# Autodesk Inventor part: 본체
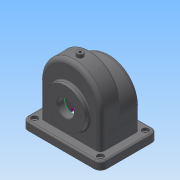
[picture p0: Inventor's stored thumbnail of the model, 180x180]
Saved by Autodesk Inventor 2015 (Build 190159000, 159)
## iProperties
Created: 2017-11
Part Number: 본체
Material: 알루미늄 6061
Document SubType Name: Modeling
Designer: user
Density: 2.7 g/cm^3
Appearance: 연회색
Mass: 1083.79 g
Surface Area: 1185.38 cm^2
Volume: 401.404 cm^3
Author: user
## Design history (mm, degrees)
sketch "스케치1"
  geometry: L1 (-58, 15)-(-58, -65); L2 (-58, -65)-(58, -65); L3 (58, -65)-(58, 15); C1 r 37.5 at (0, 0); A1 r 58 centre (0, 15) between (58, 15) and (-58, 15)
  constraints: 6 end point, 2 centre point, 2 point on circle, 1 perpendicular, 1 tangent, 1 vertical
extrude "돌출1" new body sketch "스케치1" distance "d18" = 9; taper "d19" = 0 deg
extrude "돌출2" join sketch "스케치1" distance "d20" = 38; taper "d21" = 0 deg
node "작업 평면1"
sketch "스케치2"
  geometry: C1 r 31 at (0, 0); 1 further point
  constraints: 1 centre point, 1 coincident
extrude "돌출3" join sketch "스케치2" distance "d30" = 10; taper "d31" = 0 deg
sketch "스케치3"
  geometry: L1 (58, -8)-(58, -65); L2 (58, -65)-(-58, -65); L3 (-58, -65)-(-58, -8); A1 r 58 centre (0, -8) between (58, -8) and (-58, -8); 1 further point
  constraints: 6 end point, 2 point on circle, 1 centre point, 1 perpendicular, 1 vertical
extrude "돌출4" join sketch "스케치3" distance "d39" = 38; taper "d40" = 0 deg
sketch "스케치4"
  geometry: C1 r 37.5 at (0, 0) reference; C2 r 16 at (0, 0)
  constraints: 1 centre point, 1 coincident
  dimensions: "d41" = 32 diameter of C2
extrude "돌출5" cut sketch "스케치4" distance "d42" = 14; taper "d43" = 0 deg
sketch "스케치5"
  geometry: L1 (-53, 14.446)-(-53, -65.554); L2 (53, 14.446)-(53, -65.554); L3 (-53, -65.554)-(53, -65.554); C1 r 16 at (0, 0) reference; A1 r 53 centre (0, 14.446) between (53, 14.446) and (-53, 14.446); A2 r 53 centre (0, -8.554) between (53, -8.554) and (-53, -8.554)
  constraints: 6 end point, 4 point on circle, 2 centre point, 2 point on line, 2 tangent, 2 vertical, 1 horizontal
extrude "돌출6" cut sketch "스케치5" distance "d49" = 66; taper "d50" = 0 deg
extrude "돌출7" cut sketch "스케치5" distance "d51" = 28; taper "d52" = 0 deg
extrude "돌출8" cut sketch "스케치5" distance "d53" = 95; taper "d54" = 0 deg
sketch "스케치6"
  geometry: L1 (133, 17)-(-17, 17); L2 (-17, 17)-(-17, -93); L3 (-17, -93)-(133, -93); L4 (133, 17)-(133, -93); L5 (-17, 17)-(-17, 5); L6 (-17, 17)-(-5, 17); L7 (133, -93)-(133, -81); L8 (133, -93)-(121, -93); L9 (116, 0)-(0, 0); L10 (0, 0)-(0, -76); L11 (0, -76)-(116, -76); L12 (116, -76)-(116, 0); L13 (111, -5)-(5, -5); L14 (5, -5)-(5, -71); L15 (5, -71)-(111, -71); L16 (111, -71)-(111, -5); C1 r 6 at (121, 5); C2 r 6 at (121, -81); C3 r 6 at (-5, -81); C4 r 6 at (-5, 5); C5 r 2.5 at (121, 5); C6 r 2.5 at (121, -81); C7 r 2.5 at (-5, -81); C8 r 2.5 at (-5, 5); 1 further point
  constraints: 32 end point, 8 centre point, 4 coincident, 4 parallel, 4 point on line, 3 perpendicular, 2 horizontal, 1 vertical
  dimensions: "d69" = 5 diameter of C5; "d70" = 5 diameter of C6; "d71" = 5 diameter of C7; "d72" = 5 diameter of C8
extrude "돌출15" join sketch "스케치6" distance "d86" = 15; taper "d87" = 0 deg
extrude "돌출16" join sketch "스케치6" distance "d88" = 10; taper "d89" = 0 deg
extrude "돌출17" join sketch "스케치6" distance "d90" = 10; taper "d91" = 0 deg
node "작업 평면3"
sketch "스케치8"
  geometry: C1 r 6 at (75, -36); 1 further point
  constraints: 1 centre point
  dimensions: "d95" = 12 diameter of C1
extrude "돌출18" join sketch "스케치8" stored distance "d96" = 0; taper "d97" = 0 deg
hole "구멍1" sketch "스케치8" diameter "d98" = 4.459; stored, may be unused: countersink angle "d102" = 82 deg, drill point angle "d104" = 118 deg; dims "d99" = 10, "d100" = 3.023, "d101" = 2, "d103" = 12.8
sketch "스케치9"
  geometry: L1 (0, 29)-(0, -29); L2 (-29, 0)-(29, 0); C1 r 37.5 at (0, 0) reference; A1 r 29 centre (0, 0) between (0, 29) and (0, -29)
  constraints: 4 end point, 4 point on circle, 1 centre point, 1 coincident, 1 perpendicular, 1 vertical
  dimensions: "d105" = 58 diameter of A1
hole "구멍2" sketch "스케치9" at (0, 29), (-29, 0), (29, 0), (0, -29) diameter "d106" = 2.459; stored, may be unused: countersink angle "d110" = 82 deg, drill point angle "d112" = 118 deg; dims "d107" = 6, "d108" = 3.023, "d109" = 2, "d111" = 8
sketch "스케치10"
  geometry: L1 (0, 26)-(0, -26); L2 (-26, 0)-(26, 0); C1 r 31 at (0, 0) reference; A1 r 26 centre (0, 0) between (0, 26) and (0, -26)
  constraints: 4 end point, 4 point on circle, 1 centre point, 1 coincident, 1 perpendicular, 1 vertical
  dimensions: "d113" = 52 diameter of A1
hole "구멍3" sketch "스케치10" at (0, 26), (-26, 0), (26, 0), (0, -26) diameter "d114" = 2.459; stored, may be unused: countersink angle "d118" = 82 deg, drill point angle "d120" = 118 deg; dims "d115" = 6, "d116" = 3.023, "d117" = 2, "d119" = 8
sketch "스케치11" dims "d52" = 0, "d71" = 5
  geometry: L1 (93, -80)-(-17, -80) reference; L2 (-7.073, -36.398)-(83.073, -36.398); L3 (83.073, -36.398)-(83.073, -43.602); L4 (83.073, -43.602)-(-7.073, -43.602); L5 (-7.073, -43.602)-(-7.073, -36.398); 1 further point
  constraints: 2 other
feature "엠보싱1" sketch "스케치11" dims "d125" = 0.5, "d126" = 0
fillet "모깎기1" dims "d127" = 3
fillet "모깎기2" dims "d128" = 8
fillet "모깎기3" dims "d129" = 12
fillet "모깎기4" dims "d130" = 3
chamfer "모따기1" distance "d131" = 1; stored, may be unused: second distance "d132" = 2, angle "d133" = 45 deg
chamfer "모따기2" distance "d134" = 1; stored, may be unused: second distance "d135" = 2, angle "d136" = 45 deg
node "솔리드1"
other parameters: "d22" = 48, "d26" = 116, "d92" = -144
